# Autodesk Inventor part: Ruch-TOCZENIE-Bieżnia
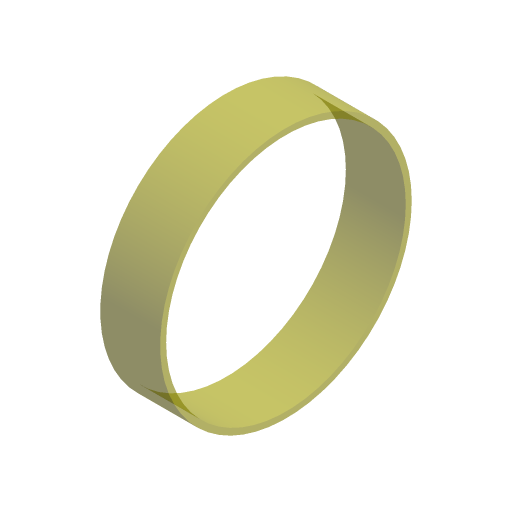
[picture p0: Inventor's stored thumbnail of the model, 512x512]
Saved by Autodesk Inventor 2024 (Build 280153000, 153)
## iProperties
Company: ATC
Created: 2023-03
Part Number: Ruch-TOCZENIE-Bieżnia
Document SubType Name: Modeling
Designer: Andrzej Jaskulski
Manufacturer: Standard
Standards Organization: Custom
Material: Kurs-AJ
Stock Number: Ruch-TOCZENIE-Bieżnia
Density: 1 g/cm^3
Appearance: Przezroczyste — żółte
Checked By: A.J.
Engr Approved By: Andrzej Jaskulski
Mfg Approved By: Andrzej Jaskulski
Authority: A.J.
DEB: 60,000 mm
Title: A.J.: Kurs R2024-MEP
Author: Andrzej Jaskulski
Revision Number: 1/24
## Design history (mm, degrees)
sketch "Sketch2"
  geometry: C1 r 30 at (0, 0); C2 r 31.5 at (0, 0)
  constraints: 2 centre point, 1 coincident
  dimensions: "DEB" = 60 diameter of C1; "d20" = 1.5 radial gap between concentric circles of C1 C2
extrude "Extrusion2" new body sketch "Sketch2" distance "d6" = 15; taper "d7" = 0 deg
node "Bryła1"
node "Korpusy bryłowe"
node "Korpusy powierzchniowe"
